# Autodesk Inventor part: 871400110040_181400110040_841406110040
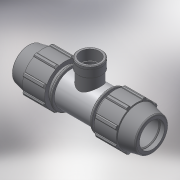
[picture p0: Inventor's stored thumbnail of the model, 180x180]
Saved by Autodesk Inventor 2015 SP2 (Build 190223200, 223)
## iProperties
Created: 2017-02
Part Number: 871400110040_181400110040_841406110040
Material: Generic
Description: PLASSON TEE WITH THREADED FEMALE OFFTAKE 110-4"-110
Document SubType Name: Modeling
Designer: KIM
Mass: 92.6774 g
Surface Area: 199.44 cm^2
Volume: 66.1981 cm^3
Density: 1 g/cm^3
Appearance: Default
Author: KIM
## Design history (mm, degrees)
derived "87140.ipt"
feature "Solid1::87140.ipt"
feature "Solid2::87140.ipt"
tag "TaggingFeature1"
body "Solid1"
other parameters: "d4" = 21.5, "d5" = 61.92, "d7" = 181, "d11" = 8.6, "d13" = 120 deg, "d14" = 143, "d15" = 10 deg, "d16" = 157.47, "d18" = 5.5, "d19" = 35 deg, "d20" = 17.5 deg, "d21" = 168.33, "d23" = 0, "d25" = 360 deg, "d27" = 3.62, "d33" = 2.2, "d42" = 92.88, "d43" = 5.43, "d46" = 3.3, "d68" = 15.48, "d76" = 110.072, "d80" = 3.30216, "d91" = 135.75, "d95" = 99, "d112" = 52, "d115" = 137.59, "d116" = 135 deg, "d117" = 126.5828, "d118" = 516, "d119" = 99, "d121" = 0, "d122" = 99, "d124" = 0, "d128" = 0, "d129" = 11, "d130" = 15.6, "d131" = 0.3, "d132" = 0.3, "d133" = 137.59, "E_" = 181, "l_2" = 52, "Rp_" = 110.072, "H_" = 516
